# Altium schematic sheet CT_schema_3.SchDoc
size 461 x 297 mm
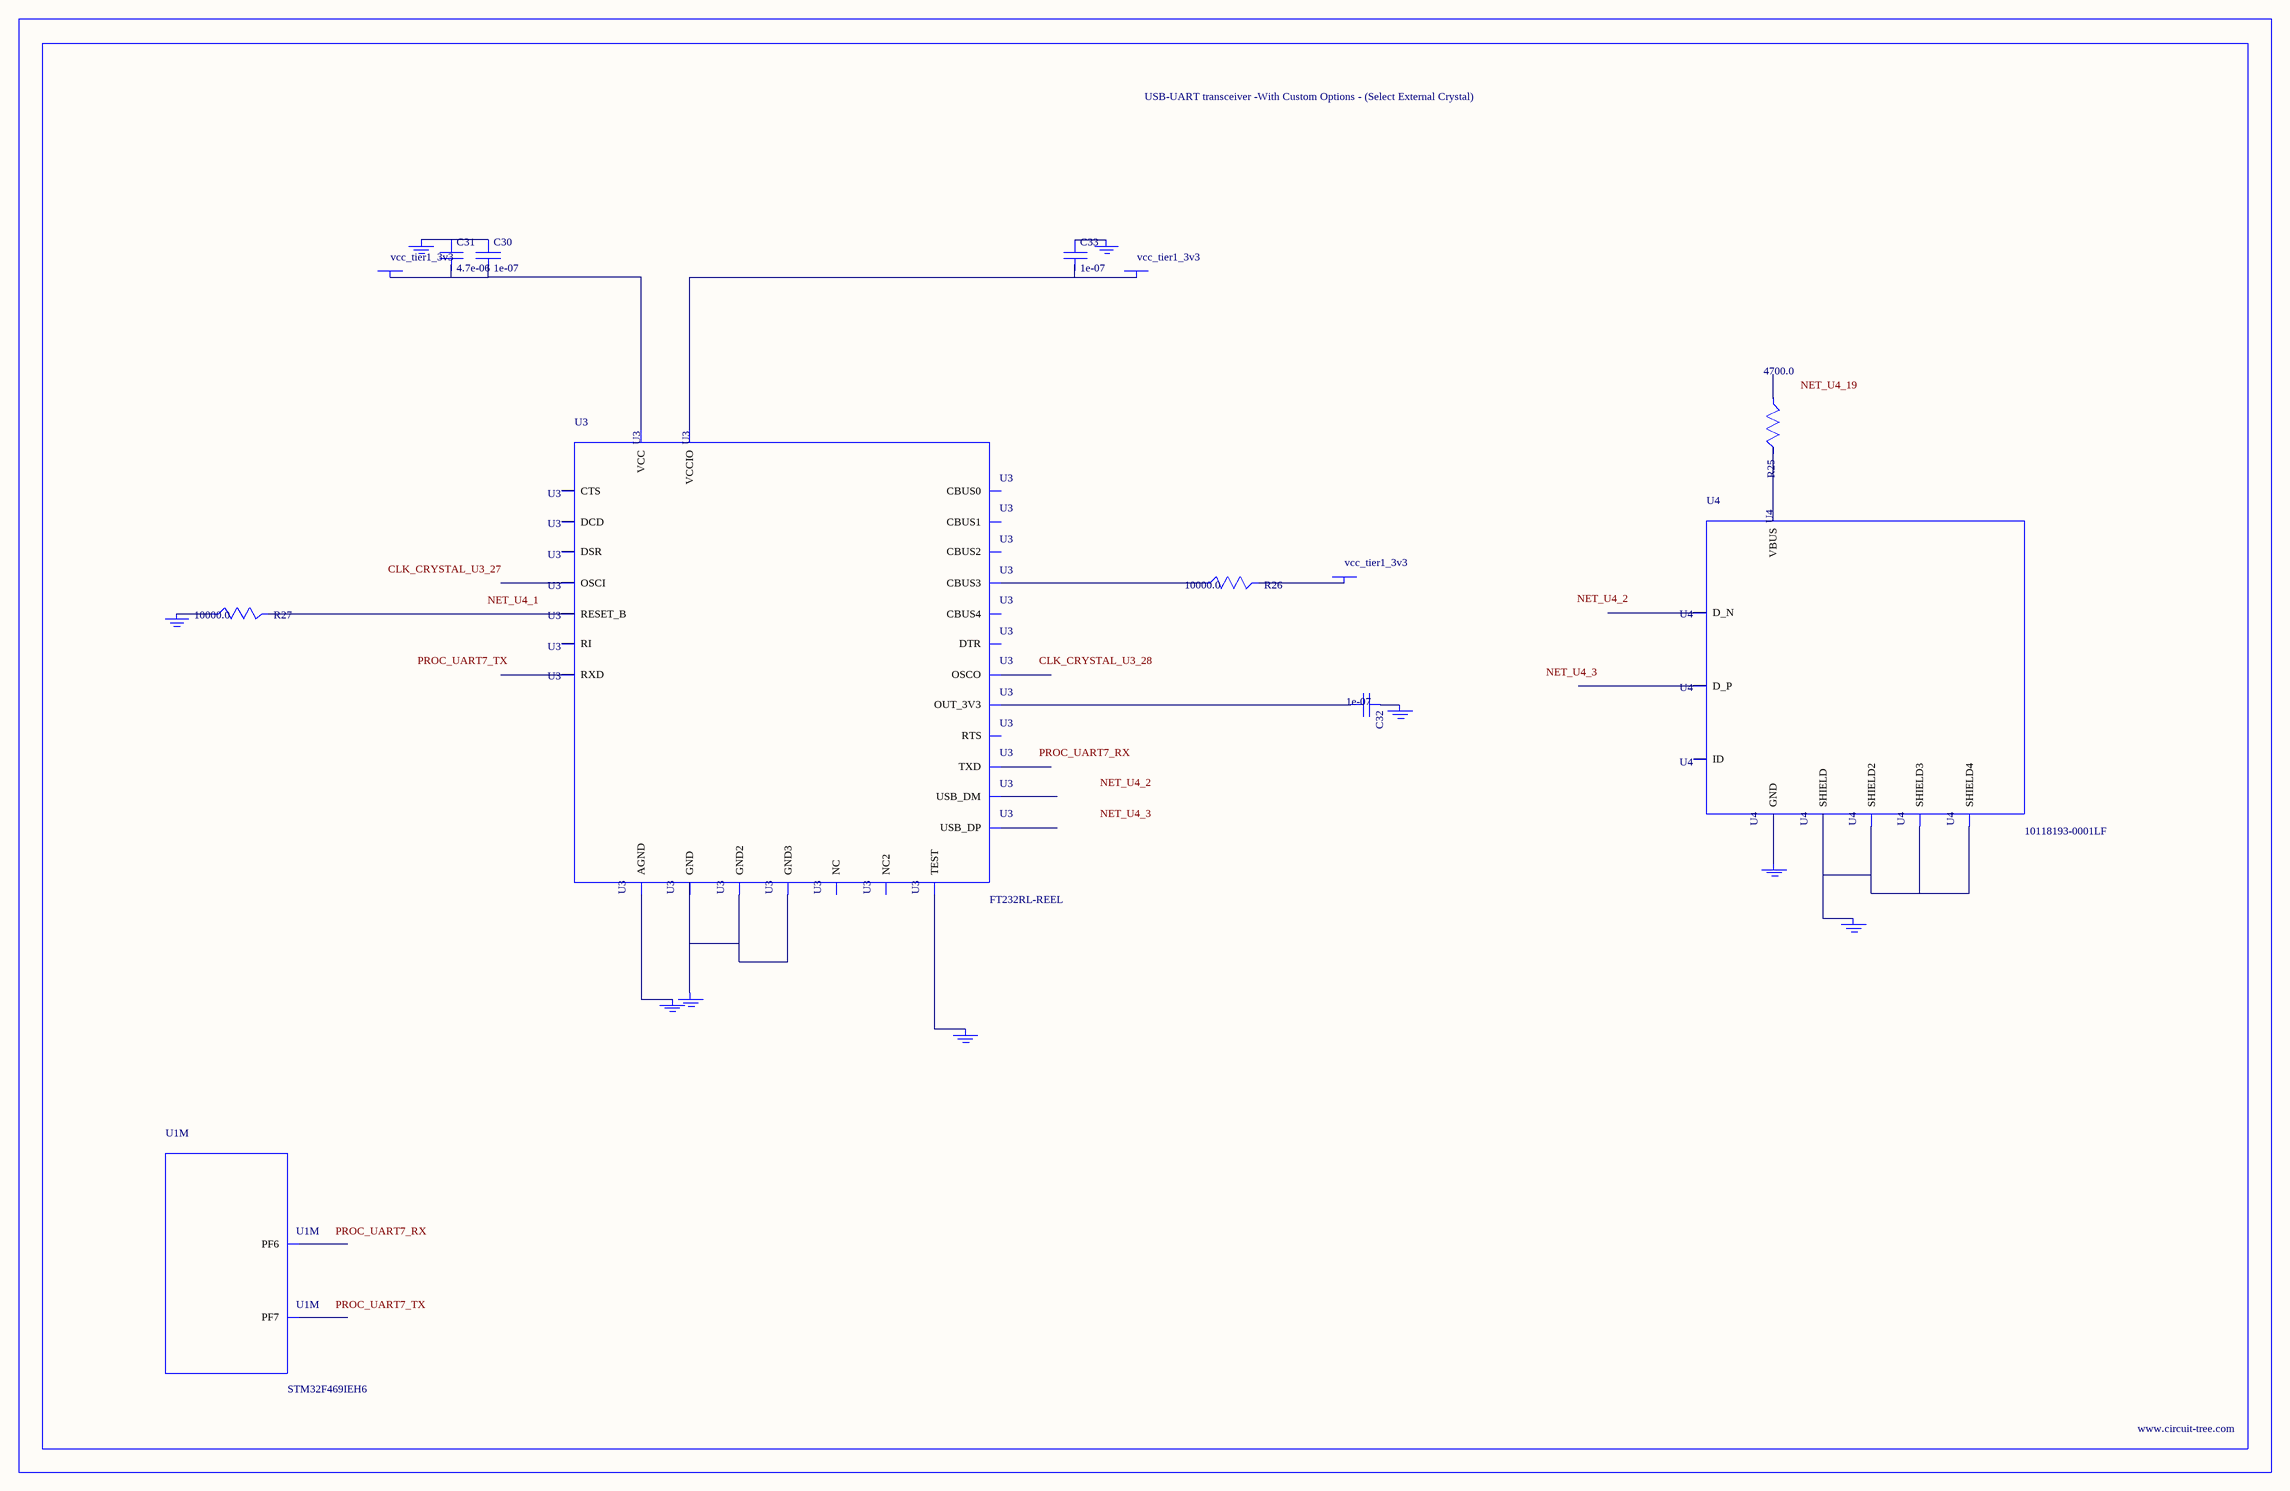
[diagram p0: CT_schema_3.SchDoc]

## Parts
BORDER2  (no value)
C30  1e-07  [C0402]
C31  4.7e-06  [C0805]
C32  1e-07  [C0402]
C33  1e-07  [C0402]
GND_INSTANCE_2_0  (no value)
GND_INSTANCE_2_1  (no value)
GND_INSTANCE_2_2  (no value)
GND_INSTANCE_2_3  (no value)
GND_INSTANCE_2_4  (no value)
GND_INSTANCE_2_5  (no value)
GND_INSTANCE_2_6  (no value)
GND_INSTANCE_2_7  (no value)
GND_INSTANCE_2_8  (no value)
POWER_INSTANCE_2_0  vcc_tier1_3v3
POWER_INSTANCE_2_1  vcc_tier1_3v3
POWER_INSTANCE_2_2  vcc_tier1_3v3
R25  4700.0  [R0603]
R26  10000.0  [R0603]
R27  10000.0  [R0603]
U1  STM32F469IEH6  [UFBGA176]  (part M of 16)
U3  FT232RL-REEL  [SSOP-28]
U4  10118193-0001LF  [FCI_10118193-0001LF]

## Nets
NetC30_1: C30.1 C31.1 GND_INSTANCE_2_3.0(GND)
NetC30_2: C30.2 C31.2 POWER_INSTANCE_2_2.0(PWR) U3.20(VCC)
NetC32_1: C32.1 GND_INSTANCE_2_1.0(GND)
NetC32_2: C32.2 U3.17(OUT_3V3)
NetC33_1: C33.1 GND_INSTANCE_2_0.0(GND)
NetC33_2: C33.2 POWER_INSTANCE_2_0.0(PWR) U3.4(VCCIO)
NetGND_INSTANCE_2_2_0: GND_INSTANCE_2_2.0(GND) R27.1
NetGND_INSTANCE_2_4_0: GND_INSTANCE_2_4.0(GND) U3.25(AGND)
NetGND_INSTANCE_2_5_0: GND_INSTANCE_2_5.0(GND) U3.26(TEST)
NetGND_INSTANCE_2_6_0: GND_INSTANCE_2_6.0(GND) U3.7(GND) U3.18(GND2) U3.21(GND3)
NetGND_INSTANCE_2_7_0: GND_INSTANCE_2_7.0(GND) U4.6(SHIELD) U4.7(SHIELD2) U4.8(SHIELD3) U4.9(SHIELD4)
NetGND_INSTANCE_2_8_0: GND_INSTANCE_2_8.0(GND) U4.5(GND)
NetPOWER_INSTANCE_2_1_0: POWER_INSTANCE_2_1.0(PWR) R26.2
NetR25_2: R25.2 U4.1(VBUS)
NetR26_1: R26.1 U3.14(CBUS3)
NetR27_2: R27.2 U3.19(RESET_B)

Not connected (* = marked no-connect by the designer): R25 1; U1 K1(PF7) K2(PF6); U3 1(TXD) 2(DTR) 3(RTS) 5(RXD) 6(RI) 8(NC) 9(DSR) 10(DCD) 11(CTS) 12(CBUS4) 13(CBUS2) 15(USB_DP) 16(USB_DM) 22(CBUS1) 23(CBUS0) 24(NC2) 27(OSCI) 28(OSCO); U4 2(D_N) 3(D_P) 4(ID)

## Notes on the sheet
- Labels drawn without touching a wire or pin: CLK_CRYSTAL_U3_27, CLK_CRYSTAL_U3_28, NET_U4_1, NET_U4_2, NET_U4_3, NET_U4_19, PROC_UART7_RX, PROC_UART7_TX

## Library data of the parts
BORDER2 = BORDER_PAGE2
C30 C32 C33 = C0402C104K3RACTU
C31 = C0805C475K4RACTU
GND_INSTANCE_2_0-GND_INSTANCE_2_8 = GND
POWER_INSTANCE_2_0-POWER_INSTANCE_2_2 = PWR
R25 = RC0603JR-074K7L
R26 R27 = RC0603JR-0710KL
